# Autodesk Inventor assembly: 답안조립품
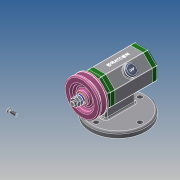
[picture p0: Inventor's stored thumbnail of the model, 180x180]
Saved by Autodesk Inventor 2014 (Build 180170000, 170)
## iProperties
Created: 2021-02
Part Number: 답안조립품
Document SubType Name: Assembly
Designer: kbl
Author: kbl
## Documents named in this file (14)
- C:\Users\kbl\Desktop\710204V1028\답안조립품.iam
- C:\Users\kbl\Desktop\710204V1028\본체.ipt
- C:\Users\kbl\Desktop\710204V1028\V벨트풀리.ipt
- C:\Users\kbl\Desktop\710204V1028\고무캡.ipt
- C:\Users\kbl\Desktop\710204V1028\너트 M8.ipt
- C:\Users\kbl\Desktop\710204V1028\뒤커버.ipt
- C:\Users\kbl\Desktop\710204V1028\베어링 15 x 32 x 9.ipt
- C:\Users\kbl\Desktop\710204V1028\볼트 M4 x 12.ipt
- C:\Users\kbl\Desktop\710204V1028\스프링와셔 8.ipt
- C:\Users\kbl\Desktop\710204V1028\앞커버.ipt
- C:\Users\kbl\Desktop\710204V1028\오일 실 15 25 7.ipt
- C:\Users\kbl\Desktop\710204V1028\와셔 8x17.ipt
- C:\Users\kbl\Desktop\710204V1028\축.ipt
- C:\Users\kbl\Desktop\710204V1028\키 3 x 3 x 12.ipt
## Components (2 placed, 2 different names)
1. V벨트풀리:1
2. 고무캡:1 — 각도:2
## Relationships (1: Angle 1)
- 각도:2 [Angle]: 고무캡:1
